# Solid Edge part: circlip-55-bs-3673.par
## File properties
Title: External circlip for shaft Ø55 - BS 3673
Author: TraceParts S.A.
Template: Iso Metric Part.par
Last saved by: Nimesh.N
Revision: 3
Application: TraceParts
Company: TraceParts S.A.
Density: 7833.000 kg/m^3
Accuracy: 0.990
REFERENCE: BS 3673 - d 55 - d2 52
STANDARD: BS 3673
DESIGN: External circlip for shaft Ø55 - BS 3673
OMNICLASS23: 23.13.23.11.13.25
TraceParts.PartStandardAcronym: BS
TraceParts.PartStatus: Published
TraceParts.PartNumber: 10-08012002-076217
TraceParts.InstanceId: 10-08012002-0762175FFAWK2067J1PBY7J25V4DJRX
TraceParts.PartLanguage: en
TraceParts.PartTitle: External circlip
TraceParts.PartVersion: 1.3.0
TRACEPARTS: TRACEPARTS
TraceParts.ClassPath: BS:10-08012002-076217
Username: Nimesh.N
Material: Steel
Face Style: Steel
Fill Style: ANSI32(Steel)
Virtual Style: Machined steel
Grouping: Metals\Steel
LibraryName: Materials
Coef. of Thermal Exp: 1.3e-05
Thermal Conductivity: 32.0
Specific Heat: 481.0
Modulus of Elasticity: 199947953000.0
Poisson's Ratio: 0.29
Yield Stress: 262000766.0
Ultimate Stress: 358527364.0
Elongation: 0.0
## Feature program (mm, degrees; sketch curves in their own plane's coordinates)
body "unnamed Body 1"
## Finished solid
Body 1: solid body, 16 faces, 40 edges, 28 vertices.
  Faces by surface: cylinder 8, plane 8
  Edges by curve: line 24, circle 16
Bounding box of the edges (mm): 59.200 x 64.610 x 2.000, from (-29.6, -33.21, 0) to (29.6, 31.4, 2).
Cylindrical faces by radius (mm): R1.25 x2, R3.9847 x4, R26 x1, R29.6 x1
Planar faces by outward normal: +x 2, +z 1, -x 2, -y 2, -z 1
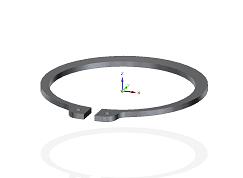
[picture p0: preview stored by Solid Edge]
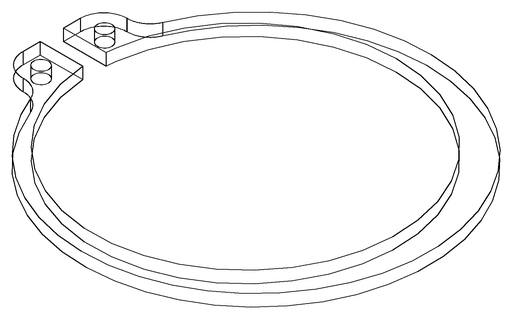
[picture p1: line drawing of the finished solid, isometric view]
